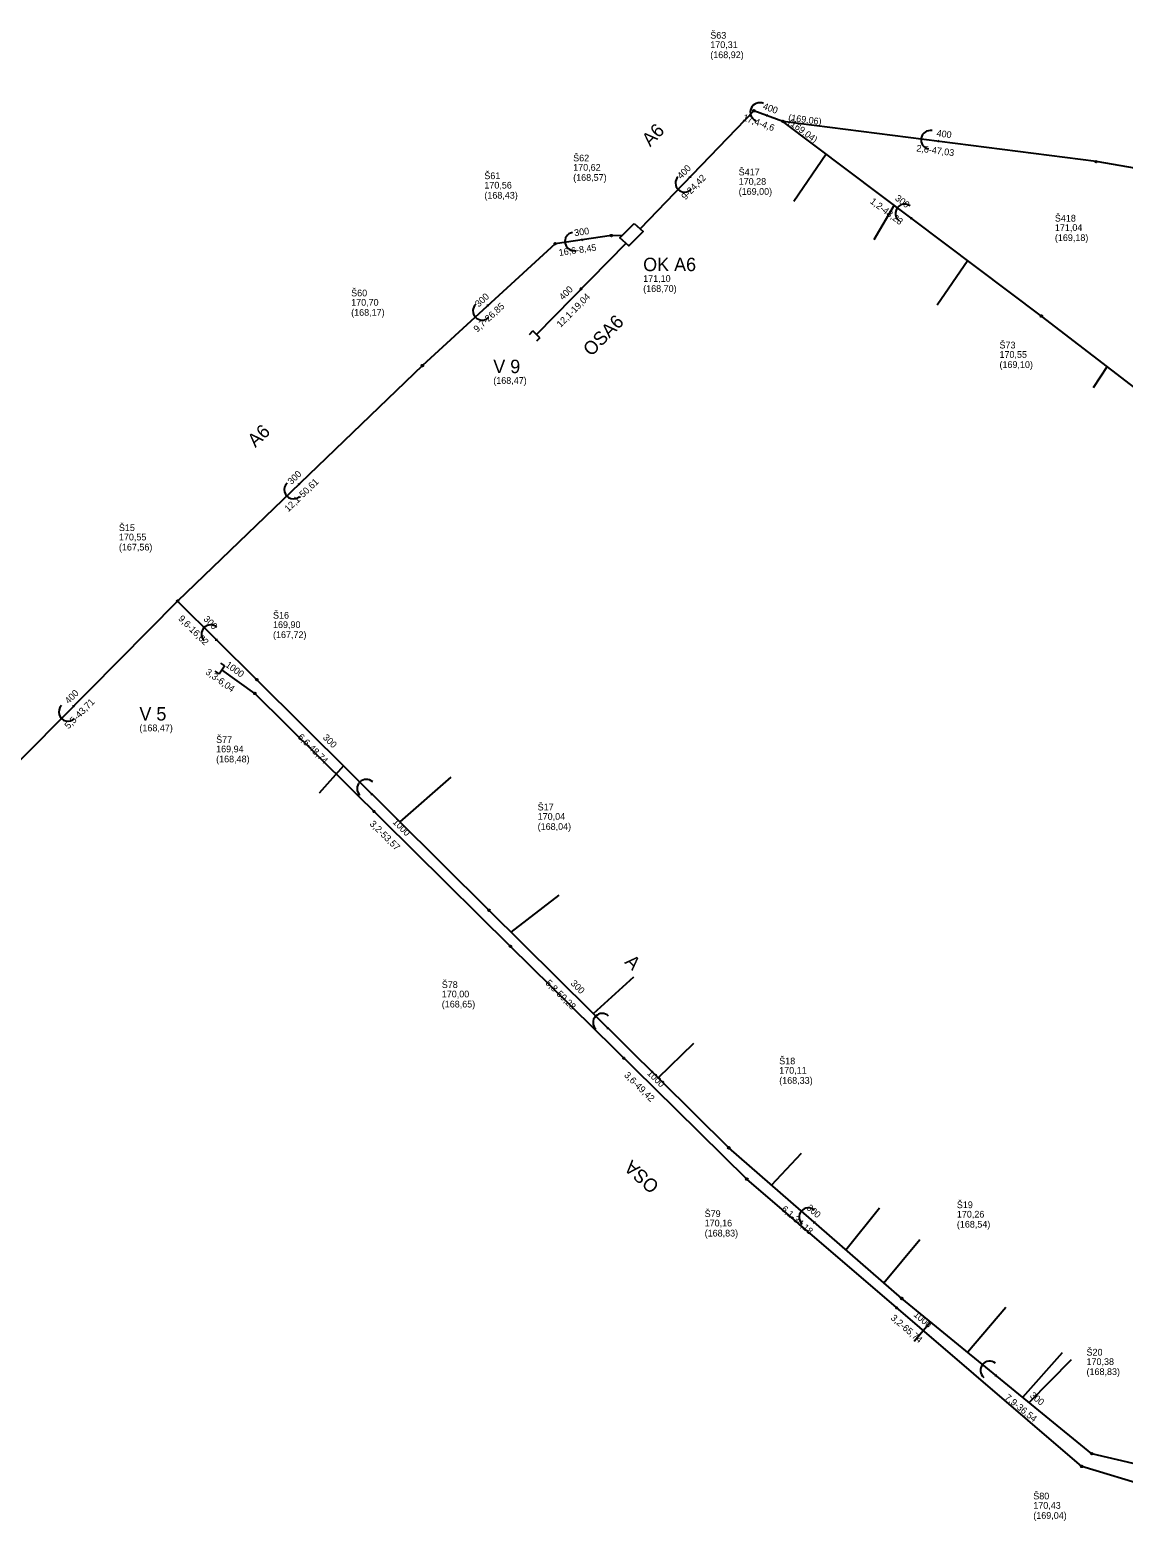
# Model space of a CAD drawing. Extents: x -548529 to -543591, y -1201432 to -1192608.
# Drawn here: x -547126.7 to -546963.8, y -1194982.4 to -1194757.8 of the extents above; entities that cross this region are included whole.
import ezdxf

# ---------------------------------------------------------------- set-up
doc = ezdxf.new("R2010")
doc.units = 0
for name, color, linetype in [('C3D_Bod-Značky', 7, 'Continuous'), ('C3D_Koridor', 7, 'Continuous'), ('C3D_Křižovatka', 7, 'Continuous'), ('C3D_Netisknutelná', 7, 'Continuous'), ('C3D_Povrch-Vrstevnice', 7, 'Continuous'), ('C3D_PP-Navrh', 7, 'Continuous'), ('C3D_PP-Popisek', 7, 'Continuous'), ('C3D_PP-zobrazeni v PR', 7, 'Continuous'), ('C3D_PR-Popisek', 7, 'Continuous'), ('C3D_SPR-Popisek', 7, 'Continuous'), ('C3D_Tlakove_potrubi_Popis', 7, 'Continuous'), ('C3D_ZPR-Formaty', 7, 'Continuous')]:
    doc.layers.add(name, color=color, linetype=linetype)

# ---------------------------------------------------------------- blocks, each defined once
blk = doc.blocks.new('100')
at = {"layer": 'Defpoints'}
blk.add_circle((0, 0), 0.127, dxfattribs=at)
blk = doc.blocks.new('96')
at = {"layer": 'Defpoints'}
for p, q in [((0, 0.72), (0, -0.72)), ((0, 0.72), (0.72, 0.72)), ((0.72, -0.72), (0, -0.72))]:
    blk.add_line(p, q, dxfattribs=at)
blk = doc.blocks.new('92')
at = {"layer": 'Defpoints'}
for points in [[(-0.11, 0.138), (0, 0), (-0.11, -0.136)], [(0.039, 0.138), (0.149, 0), (0.039, -0.136)]]:
    blk.add_lwpolyline(points, dxfattribs=at)
blk = doc.blocks.new('86')
at = {"layer": 'Defpoints'}
blk.add_lwpolyline([(0.08, 0.14), (0.19, 0), (0.08, -0.14)], dxfattribs=at)
blk.add_arc((1.37, 0), 1.37, 270, 90, dxfattribs=at)
blk = doc.blocks.new('87')
at = {"layer": 'Defpoints'}
for points in [[(-0.11, 0.138), (0, 0), (-0.11, -0.136)], [(0.039, 0.138), (0.149, 0), (0.039, -0.136)]]:
    blk.add_lwpolyline(points, dxfattribs=at)

msp = doc.modelspace()

# ---------------------------------------------------------------- linework, layer by layer
at = {"layer": 'C3D_Bod-Značky'}
for points in [[(-547018.91, -1194769.81), (-547030.715, -1194782.102), (-547035.839, -1194787.403)], [(-547014.59, -1194771.39), (-547018.91, -1194769.81)], [(-546967.94, -1194777.39), (-547014.59, -1194771.39)], [(-546976.071, -1194800.407), (-547014.59, -1194771.39)], [(-546937.35, -1194782.69), (-546967.94, -1194777.39)], [(-547048.49, -1194789.62), (-547068.27, -1194807.78)], [(-547040.13, -1194788.41), (-547048.49, -1194789.62)], [(-547038.565, -1194788.444), (-547040.13, -1194788.41)], [(-546939.08, -1194828.823), (-546976.071, -1194800.407)], [(-547068.27, -1194807.78), (-547104.74, -1194842.87)], [(-547104.74, -1194842.87), (-547135.48, -1194873.94)], [(-547092.94, -1194854.58), (-547104.74, -1194842.87)], [(-547058.36, -1194888.93), (-547092.94, -1194854.58)], [(-547022.65, -1194924.33), (-547058.36, -1194888.93)], [(-546996.87, -1194946.78), (-547022.65, -1194924.33)], [(-546968.576, -1194969.904), (-546996.87, -1194946.78)], [(-546931.82, -1194978.525), (-546968.576, -1194969.904)]]:
    msp.add_lwpolyline(points, dxfattribs=at)
at = {"layer": 'C3D_Koridor'}
for points in [[(-547008.113, -1194776.269), (-547012.932, -1194783.335)], [(-546997.986, -1194783.898), (-547001.036, -1194789.018)], [(-546987.05, -1194792.137), (-546991.598, -1194798.752)], [(-546966.29, -1194807.921), (-546968.392, -1194811.079)], [(-547080.018, -1194867.416), (-547083.647, -1194871.503)], [(-547071.596, -1194875.782), (-547064.017, -1194869.099)], [(-547055.074, -1194892.187), (-547047.908, -1194886.687)], [(-547042.817, -1194904.338), (-547036.806, -1194898.865)], [(-547033.173, -1194913.899), (-547027.84, -1194908.714)], [(-547016.257, -1194929.898), (-547011.806, -1194925.124)], [(-547005.218, -1194939.51), (-547000.214, -1194933.282)], [(-546999.558, -1194944.439), (-546994.17, -1194937.99)], [(-546987.072, -1194954.788), (-546981.401, -1194948.069)], [(-546992.573, -1194950.292), (-546995.044, -1194953.184)], [(-546978.86, -1194961.499), (-546972.949, -1194954.818)], [(-546977.88, -1194962.3), (-546971.616, -1194955.882)]]:
    msp.add_lwpolyline(points, dxfattribs=at)
at = {"layer": 'C3D_Povrch-Vrstevnice'}
for points in [[(-547037.937, -1194789.553), (-547051.291, -1194803.123)], [(-547093.231, -1194856.632), (-547098.15, -1194853.12)], [(-547055.163, -1194894.318), (-547069.52, -1194880.105), (-547093.231, -1194856.632)], [(-547019.956, -1194928.993), (-547030.499, -1194918.609), (-547055.163, -1194894.318)], [(-546970.068, -1194971.803), (-546994.182, -1194951.111), (-547019.956, -1194928.993)], [(-546934.854, -1194982.443), (-546939.511, -1194981.036), (-546970.068, -1194971.803)]]:
    msp.add_lwpolyline(points, dxfattribs=at)
at = {"layer": 'C3D_PP-Navrh'}
msp.add_lwpolyline([(-547036.73, -1194786.6), (-547035.41, -1194787.79), (-547037.53, -1194789.92), (-547038.85, -1194788.73), (-547036.73, -1194786.6)], dxfattribs=at)

# ---------------------------------------------------------------- block references
for p, xscale, yscale, rotation in [((-547051.291, -1194803.123), 1.0000000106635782, 1.0000000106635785, -134.00000165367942), ((-547098.15, -1194853.12), 1.000000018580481, 1.000000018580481, 144.99999976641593)]:
    msp.add_blockref('96', p, dxfattribs=dict(at, xscale=xscale, yscale=yscale, rotation=rotation))
at = {"layer": 'C3D_PP-zobrazeni v PR'}
for p, xscale, yscale, rotation in [((-547018.91, -1194769.81), 1.0009848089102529, 1.000984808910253, 14.224326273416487), ((-547014.59, -1194771.39), 1.0028916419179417, 1.0028916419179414, -13.69720873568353), ((-546967.94, -1194777.39), 1.0092050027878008, 1.0092050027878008, -11.116918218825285), ((-547040.13, -1194788.41), 1.0000000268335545, 1.0000000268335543, -176.00000028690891), ((-547048.49, -1194789.62), 1.0138865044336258, 1.0138865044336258, -152.43468640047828), ((-546976.071, -1194800.407), 0.9999999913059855, 0.9999999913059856, -37.00000193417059), ((-547068.27, -1194807.78), 1.0000000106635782, 1.0000000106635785, -135.99999834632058), ((-547092.94, -1194854.58), 1.0000000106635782, 1.0000000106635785, 135.99999834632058), ((-547093.231, -1194856.632), 1.0000000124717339, 1.0000000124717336, 139.99999868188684), ((-547058.36, -1194888.93), 1.0000000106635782, 1.0000000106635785, 135.99999834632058), ((-547055.163, -1194894.318), 1.0000000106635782, 1.0000000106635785, 135.99999834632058), ((-547022.65, -1194924.33), 1.0000000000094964, 1.0000000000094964, 137.9999986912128), ((-547019.956, -1194928.993), 1.0000000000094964, 1.0000000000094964, 137.9999986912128), ((-546996.87, -1194946.78), 1.0000000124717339, 1.0000000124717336, 139.99999868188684), ((-546968.576, -1194969.904), 1.0138865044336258, 1.0138865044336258, 152.43468640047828), ((-546970.068, -1194971.803), 1.0072562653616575, 1.0072562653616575, 151.23333487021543)]:
    msp.add_blockref('100', p, dxfattribs=dict(at, xscale=xscale, yscale=yscale, rotation=rotation))
at = {"layer": 'C3D_PP-zobrazeni v PR', "rotation": 90}
msp.add_blockref('100', (-547104.74, -1194842.87), dxfattribs=at)
at = {"layer": 'C3D_SPR-Popisek'}
for name, p, xscale, yscale, rotation in [('86', (-547016.75, -1194770.6), 1.0296949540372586, 1.0296949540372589, 155.86620948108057), ('86', (-546991.265, -1194774.39), 1.0098116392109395, 1.0098116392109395, 169.38969821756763), ('86', (-547028.283, -1194779.57), 1.00000000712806, 1.00000000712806, -133.00000056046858), ('86', (-546995.33, -1194785.899), 1.000000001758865, 1.000000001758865, 144.00000066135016), ('86', (-547044.31, -1194789.015), 1.008377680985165, 1.0083776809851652, -168.37362119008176), ('87', (-547044.614, -1194796.338), 1.0000000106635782, 1.0000000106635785, -134.00000165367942), ('86', (-547058.38, -1194798.7), 1.00000000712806, 1.00000000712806, -136.99999943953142), ('86', (-547086.505, -1194825.325), 1.0000000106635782, 1.0000000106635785, -135.99999834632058), ('86', (-547098.84, -1194848.725), 1.0000000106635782, 1.0000000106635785, 135.99999834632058), ('86', (-547120.11, -1194858.405), 1.0000000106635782, 1.0000000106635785, -134.00000165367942), ('86', (-547075.65, -1194871.755), 1.0000000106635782, 1.0000000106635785, 135.99999834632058), ('92', (-547075.442, -1194874.242), 1.0000000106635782, 1.0000000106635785, 135.99999834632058), ('86', (-547040.505, -1194906.63), 1.0000000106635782, 1.0000000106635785, 135.99999834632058), ('92', (-547038.242, -1194910.983), 1.0000000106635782, 1.0000000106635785, 135.99999834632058), ('86', (-547009.76, -1194935.555), 1.0000000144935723, 1.0000000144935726, 139.00000089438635), ('92', (-546997.598, -1194948.179), 1.0000000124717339, 1.0000000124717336, 139.99999868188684), ('86', (-546982.723, -1194958.342), 1.000000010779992, 1.0000000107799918, 141.00000108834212)]:
    msp.add_blockref(name, p, dxfattribs=dict(at, xscale=xscale, yscale=yscale, rotation=rotation))

# ---------------------------------------------------------------- texts
at = {"layer": 'C3D_Křižovatka'}
for s, p in [('Š63', (-547025.4, -1194759.07)), ('Š62', (-547045.82, -1194777.35)), ('Š61', (-547059.05, -1194780)), ('Š417', (-547021.17, -1194779.44)), ('Š418', (-546974.07, -1194786.32)), ('Š60', (-547078.89, -1194797.46)), ('Š73', (-546982.321, -1194805.227)), ('Š15', (-547113.48, -1194832.43)), ('Š16', (-547090.53, -1194845.48)), ('Š77', (-547099.001, -1194864.002)), ('Š17', (-547051.11, -1194874.06)), ('Š78', (-547065.393, -1194900.518)), ('Š18', (-547015.13, -1194911.89)), ('Š19', (-546988.67, -1194933.32)), ('Š79', (-547026.236, -1194934.643)), ('Š20', (-546969.356, -1194955.284)), ('Š80', (-546977.288, -1194976.713))]:
    msp.add_text(s, height=1, dxfattribs=at).set_placement(p)
at = {"layer": 'C3D_Netisknutelná'}
for s, rotation, p in [('A6', 46.16, (-547034.353, -1194775.255)), ('OSA6', 45.46, (-547043.134, -1194806.512)), ('A6', 43.9, (-547093.16, -1194820.064)), ('A', 315.25, (-547038.255, -1194896.748)), ('OSA', 137.92, (-547032.87, -1194929.831))]:
    msp.add_text(s, height=2, rotation=rotation, dxfattribs=at).set_placement(p)
at = {"layer": 'C3D_PP-Popisek'}
for s, height, p in [('OK A6', 2, (-547035.395, -1194793.707)), ('171,10 ', 1, (-547035.395, -1194795.307)), ('(168,70)', 1, (-547035.395, -1194796.807)), ('V 9', 2, (-547057.721, -1194808.903)), ('(168,47)', 1, (-547057.721, -1194810.503)), ('V 5', 2, (-547110.43, -1194860.66)), ('(168,47)', 1, (-547110.43, -1194862.26))]:
    msp.add_text(s, height=height, dxfattribs=at).set_placement(p)
at = {"layer": 'C3D_PR-Popisek'}
for s, rotation, p in [('400', 339.91, (-547017.655, -1194769.523)), ('400', 352.67, (-546991.735, -1194773.62)), ('400', 46.16, (-547029.722, -1194780.055)), ('300', 323.01, (-546997.97, -1194783.034)), ('300', 8.24, (-547045.594, -1194788.499)), ('300', 42.56, (-547059.886, -1194799.129)), ('400', 45.46, (-547047.328, -1194798.095)), ('300', 43.9, (-547087.788, -1194825.586)), ('300', 315.22, (-547100.973, -1194845.628)), ('1000', 324.47, (-547097.704, -1194852.576)), ('400', 45.31, (-547120.947, -1194858.252)), ('300', 315.19, (-547083.19, -1194863.286)), ('1000', 315.29, (-547072.789, -1194875.882)), ('300', 315.25, (-547046.277, -1194899.92)), ('1000', 315.44, (-547034.88, -1194913.309)), ('300', 318.95, (-547011.152, -1194933.411)), ('1000', 319.37, (-546995.199, -1194949.311)), ('300', 320.74, (-546977.887, -1194961.384))]:
    msp.add_text(s, height=1, rotation=rotation, dxfattribs=at).set_placement(p)
at = {"layer": 'C3D_Tlakove_potrubi_Popis'}
for s, p in [('(168,92)', (-547025.4, -1194761.97)), ('170,31 ', (-547025.4, -1194760.47)), ('(168,57)', (-547045.82, -1194780.25)), ('170,62 ', (-547045.82, -1194778.75)), ('170,56 ', (-547059.05, -1194781.4)), ('(169,00)', (-547021.17, -1194782.34)), ('170,28 ', (-547021.17, -1194780.84)), ('(168,43)', (-547059.05, -1194782.9)), ('(169,18)', (-546974.07, -1194789.22)), ('171,04 ', (-546974.07, -1194787.72)), ('(168,17)', (-547078.89, -1194800.36)), ('170,70 ', (-547078.89, -1194798.86)), ('170,55 ', (-546982.321, -1194806.627)), ('(169,10)', (-546982.321, -1194808.127)), ('170,55 ', (-547113.48, -1194833.83)), ('(167,56)', (-547113.48, -1194835.33)), ('169,90 ', (-547090.53, -1194846.88)), ('(167,72)', (-547090.53, -1194848.38)), ('169,94 ', (-547099.001, -1194865.402)), ('(168,48)', (-547099.001, -1194866.902)), ('(168,04)', (-547051.11, -1194876.96)), ('170,04 ', (-547051.11, -1194875.46)), ('(168,65)', (-547065.393, -1194903.418)), ('170,00 ', (-547065.393, -1194901.918)), ('(168,33)', (-547015.13, -1194914.79)), ('170,11 ', (-547015.13, -1194913.29)), ('170,26 ', (-546988.67, -1194934.72)), ('(168,83)', (-547026.236, -1194937.543)), ('170,16 ', (-547026.236, -1194936.043)), ('(168,54)', (-546988.67, -1194936.22)), ('170,38 ', (-546969.356, -1194956.684)), ('(168,83)', (-546969.356, -1194958.184)), ('(169,04)', (-546977.288, -1194979.613)), ('170,43 ', (-546977.288, -1194978.113))]:
    msp.add_text(s, height=1, dxfattribs=at).set_placement(p)
at = {"layer": 'C3D_ZPR-Formaty'}
for s, rotation, p in [('17,4-4,6', 339.91, (-547020.659, -1194771.195)), ('  (169,06)   ', 352.67, (-547014.564, -1194771.192)), ('  (169,04)   ', 323.01, (-547014.47, -1194771.23)), ('2,6-47,03', 352.67, (-546994.742, -1194775.854)), ('9-24,42', 46.16, (-547029.097, -1194783.16)), ('1,2-48,23', 323.01, (-547001.689, -1194783.488)), ('16,6-8,45', 8.24, (-547047.895, -1194791.451)), ('12,1-19,04', 45.46, (-547047.68, -1194802.162)), ('9,7-26,85', 42.56, (-547060.117, -1194802.876)), ('12,1-50,61', 43.9, (-547088.247, -1194829.639)), ('9,6-16,62', 315.22, (-547104.716, -1194845.57)), ('3,3-6,04', 324.47, (-547100.682, -1194853.65)), ('5,5-43,71', 45.31, (-547120.99, -1194861.996)), ('6,6-48,74', 315.19, (-547086.932, -1194863.226)), ('3,2-53,57', 315.29, (-547076.212, -1194876.154)), ('5,8-50,28', 315.25, (-547050.02, -1194899.873)), ('3,6-49,42', 315.44, (-547038.306, -1194913.587)), ('6,1-34,18', 318.95, (-547014.897, -1194933.603)), ('3,2-65,74', 319.37, (-546998.608, -1194949.818)), ('7,9-36,54', 320.74, (-546981.623, -1194961.689))]:
    msp.add_text(s, height=1, rotation=rotation, dxfattribs=at).set_placement(p)

doc.saveas('drawing.dxf')
